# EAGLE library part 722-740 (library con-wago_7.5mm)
Serie 722, Federleiste mit geraden Einlötstiften / Series 722, Female connector with straight solder pins Polzahl / Pole No.: 10 Rastermaß / Pitch: 7.5 mm Bemessungsspannung / Rated Voltage: 630 V Nennstrom / Nominal Current: 12 A Lötstiftlänge: / Solder Pin Length: 5 mm Farbe / Color: lichtgrau / light gray Stand: 01.01.2012. Die jeweils aktuellen Daten zu diesem Artikel finden Sie in unserem Produktkatalog, den Sie unter www.wago.com einsehen können. As of: 01/01/2012. Please find the newest data for this article in our product catalogue, which can be viewed under www.wago.com.
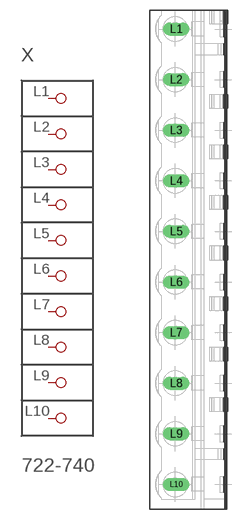
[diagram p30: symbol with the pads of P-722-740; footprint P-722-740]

Designator prefix X

## 722-740  [P-722-740]
L1  P1
L2  P2
L3  P3
L4  P4
L5  P5
L6  P6
L7  P7
L8  P8
L9  P9
L10  P10

## Footprint P-722-740 (pad centres in mm)
drill 1.3 long: L1 -2.129,34.2; L2 -2.129,26.7; L3 -2.129,19.2; L4 -2.129,11.7; L5 -2.129,4.2; L6 -2.129,-3.3; L7 -2.129,-10.8; L8 -2.129,-18.3; L9 -2.129,-25.8; L10 -2.129,-33.3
